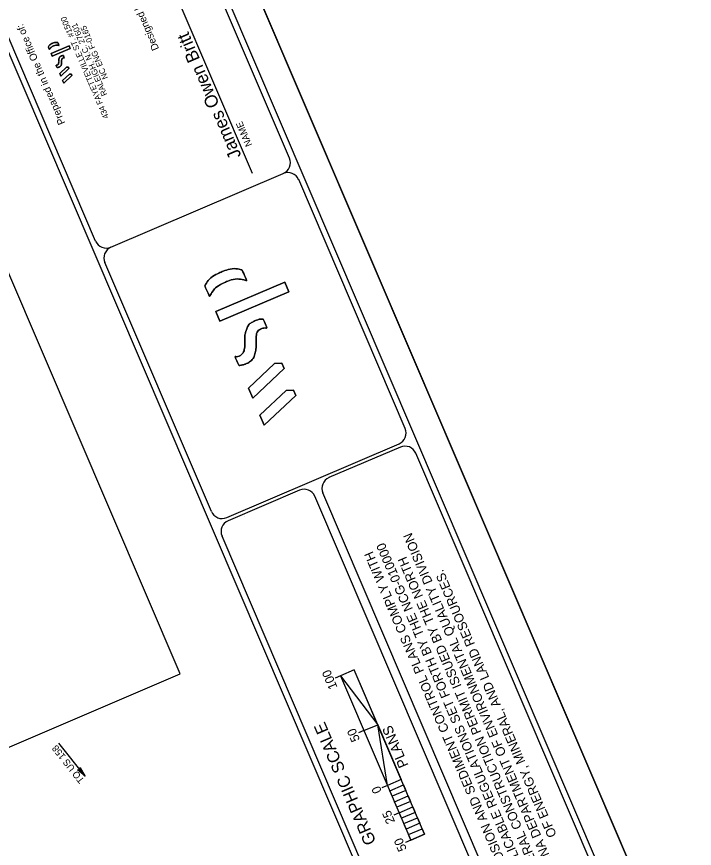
# Model space of a CAD drawing. Extents: x 1550250 to 1553148, y 808916 to 812359.
# Drawn here: x 1552151 to 1553148, y 809907 to 811132 of the extents above; entities that cross this region are included whole.
import ezdxf

# ---------------------------------------------------------------- set-up
doc = ezdxf.new("R2010")
doc.units = 0
for name, color, linetype in [('_P_RDY_Guardrail_Anchor_Unit_Cell', 7, 'Continuous'), ('Default', 7, 'Continuous'), ('Old_Level_46', 7, 'Continuous'), ('P_RDY_Bridge_Approach_Slab_Hatching', 7, 'Continuous'), ('P_RDY_Shade_Light', 7, 'Continuous'), ('Prop DSN Text', 7, 'Continuous'), ('Prop Terminator Cell', 7, 'Continuous'), ('Scratch_Level_0', 7, 'Continuous'), ('Sheet Title CELL', 7, 'Continuous'), ('Sheet_Plan_CELL', 7, 'Continuous'), ('Sheet_Title_CELL', 7, 'Continuous')]:
    doc.layers.add(name, color=color, linetype=linetype)

msp = doc.modelspace()

# ---------------------------------------------------------------- linework, layer by layer
at = {"layer": '_P_RDY_Guardrail_Anchor_Unit_Cell'}
msp.add_line((1552706.9, 809975.9), (1552727.1, 809984.5), dxfattribs=at)
for points in [[(1552627.5, 810161.4), (1552682.2, 810089.3), (1552647.7, 810170)], [(1552696.6, 810000.1), (1552682.2, 810089.3), (1552716.7, 810008.7)], [(1552703.5, 809984), (1552700, 809992), (1552720.2, 810000.7), (1552723.6, 809992.6)], [(1552710.4, 809967.8), (1552706.9, 809975.9), (1552727.1, 809984.5), (1552730.5, 809976.5)], [(1552717.3, 809951.7), (1552713.8, 809959.8), (1552734, 809968.4), (1552737.4, 809960.3)], [(1552724.2, 809935.6), (1552720.7, 809943.7), (1552740.9, 809952.3), (1552744.3, 809944.2)], [(1552731.1, 809919.5), (1552727.6, 809927.5), (1552747.8, 809936.2), (1552751.2, 809928.1)]]:
    msp.add_lwpolyline(points, close=True, dxfattribs=at)
at = {"layer": 'Default'}
for p, q in [((1552201.4, 811077.7), (1552227.9, 811089)), ((1552229.5, 811085.3), (1552203, 811074)), ((1552227.9, 811089), (1552229.5, 811085.3)), ((1552203, 811074), (1552201.4, 811077.7)), ((1552214, 811048.2), (1552224, 811057.7)), ((1552215.6, 811044.4), (1552214, 811048.2)), ((1552227.7, 811055.8), (1552215.6, 811044.4)), ((1552218.4, 811037.9), (1552228.4, 811047.3)), ((1552224, 811057.7), (1552226.8, 811057.8)), ((1552226.8, 811057.8), (1552227.7, 811055.8)), ((1552228.4, 811047.3), (1552231.2, 811047.5)), ((1552231.2, 811047.5), (1552232.1, 811045.4)), ((1552220, 811034), (1552218.4, 811037.9)), ((1552232.1, 811045.4), (1552220, 811034)), ((1552443.9, 810697.7), (1552545.5, 810741)), ((1552545.5, 810741), (1552551.5, 810726.9)), ((1552551.5, 810726.9), (1552449.9, 810683.6)), ((1552449.9, 810683.6), (1552443.9, 810697.7)), ((1552491.9, 810584.8), (1552530.4, 810621.1)), ((1552530.4, 810621.1), (1552541.3, 810621.6)), ((1552541.3, 810621.6), (1552544.6, 810613.7)), ((1552544.6, 810613.7), (1552498.2, 810570)), ((1552498.2, 810570), (1552491.9, 810584.8)), ((1552508.8, 810545.2), (1552547.3, 810581.4)), ((1552547.3, 810581.4), (1552558.1, 810581.9)), ((1552558.1, 810581.9), (1552561.5, 810574.1)), ((1552561.5, 810574.1), (1552515.1, 810530.4)), ((1552515.1, 810530.4), (1552508.8, 810545.2))]:
    msp.add_line(p, q, dxfattribs=at)
for points in [[(1552227.9, 811089), (1552201.4, 811077.7), (1552203, 811074), (1552229.5, 811085.3), (1552227.9, 811089)], [(1552214, 811048.2), (1552215.6, 811044.4), (1552227.7, 811055.8), (1552226.8, 811057.8), (1552224, 811057.7), (1552214, 811048.2)], [(1552218.4, 811037.9), (1552220, 811034), (1552232.1, 811045.4), (1552231.2, 811047.5), (1552228.4, 811047.3), (1552218.4, 811037.9)], [(1552545.5, 810741), (1552443.9, 810697.7), (1552449.9, 810683.6), (1552551.5, 810726.9), (1552545.5, 810741)], [(1552491.9, 810584.8), (1552498.2, 810570), (1552544.6, 810613.7), (1552541.3, 810621.6), (1552530.4, 810621.1), (1552491.9, 810584.8)], [(1552508.8, 810545.2), (1552515.1, 810530.4), (1552561.5, 810574.1), (1552558.1, 810581.9), (1552547.3, 810581.4), (1552508.8, 810545.2)]]:
    msp.add_lwpolyline(points, dxfattribs=at)
for points in [[(1552205.1, 811089), (1552202, 811087.8), (1552200, 811085.6), (1552199, 811083.4), (1552199, 811083.4), (1552197.2, 811087.6), (1552197.2, 811087.6), (1552198.3, 811089.7), (1552200.8, 811091.8), (1552203.4, 811092.9), (1552203.4, 811092.9), (1552203.4, 811092.9), (1552203.4, 811092.9), (1552206.1, 811094), (1552209.3, 811094.4), (1552211.5, 811093.7), (1552211.5, 811093.7), (1552213.3, 811089.6), (1552213.3, 811089.6), (1552211.1, 811090.3), (1552208.1, 811090.3), (1552205.1, 811089), (1552205.1, 811089), (1552205.1, 811089), (1552205.1, 811089)], [(1552205.1, 811089), (1552205.1, 811089), (1552205.1, 811089), (1552205.1, 811089), (1552208.1, 811090.3), (1552211.1, 811090.3), (1552213.3, 811089.6), (1552213.3, 811089.6), (1552211.5, 811093.7), (1552211.5, 811093.7), (1552209.3, 811094.4), (1552206.1, 811094), (1552203.4, 811092.9), (1552203.4, 811092.9), (1552203.4, 811092.9), (1552203.4, 811092.9), (1552200.8, 811091.8), (1552198.3, 811089.7), (1552197.2, 811087.6), (1552197.2, 811087.6), (1552199, 811083.4), (1552199, 811083.4), (1552200, 811085.6), (1552202, 811087.8), (1552205.1, 811089)], [(1552212.5, 811057.5), (1552211.8, 811057.2), (1552211, 811057), (1552210.2, 811057), (1552210.2, 811057), (1552208.8, 811060.4), (1552208.8, 811060.4), (1552209.4, 811060.4), (1552210.4, 811060.5), (1552211.2, 811061.2), (1552211.9, 811061.8), (1552212.3, 811062.6), (1552212.4, 811063.6), (1552212.6, 811064.7), (1552212.5, 811065.8), (1552212.5, 811066.9), (1552212.6, 811068.1), (1552212.6, 811069.2), (1552213, 811070.3), (1552213.5, 811071.9), (1552214.4, 811073.2), (1552216, 811074), (1552216.1, 811074), (1552216.3, 811074.1), (1552216.5, 811074.2), (1552217.5, 811074.6), (1552218.5, 811074.9), (1552219.6, 811074.8), (1552219.6, 811074.8), (1552221.1, 811071.4), (1552221.1, 811071.4), (1552220.4, 811071.5), (1552219.4, 811071.4), (1552218.7, 811071), (1552217, 811070.1), (1552216.9, 811067.5), (1552216.9, 811065.3), (1552216.9, 811065), (1552216.9, 811064.6), (1552216.9, 811064.3), (1552216.8, 811063.3), (1552216.7, 811062.4), (1552216.5, 811061.4), (1552216.2, 811060.4), (1552215.8, 811059.6), (1552215.1, 811058.9), (1552214.4, 811058.3), (1552213.6, 811057.9), (1552212.8, 811057.5), (1552212.7, 811057.5), (1552212.6, 811057.5), (1552212.5, 811057.5)], [(1552212.5, 811057.5), (1552212.6, 811057.5), (1552212.7, 811057.5), (1552212.8, 811057.5), (1552213.6, 811057.9), (1552214.4, 811058.3), (1552215.1, 811058.9), (1552215.8, 811059.6), (1552216.2, 811060.4), (1552216.5, 811061.4), (1552216.7, 811062.4), (1552216.8, 811063.3), (1552216.9, 811064.3), (1552216.9, 811064.6), (1552216.9, 811065), (1552216.9, 811065.3), (1552216.9, 811067.5), (1552217, 811070.1), (1552218.7, 811071), (1552219.4, 811071.4), (1552220.4, 811071.5), (1552221.1, 811071.4), (1552221.1, 811071.4), (1552219.6, 811074.8), (1552219.6, 811074.8), (1552218.5, 811074.9), (1552217.5, 811074.6), (1552216.5, 811074.2), (1552216.3, 811074.1), (1552216.1, 811074), (1552216, 811074), (1552214.4, 811073.2), (1552213.5, 811071.9), (1552213, 811070.3), (1552212.6, 811069.2), (1552212.6, 811068.1), (1552212.5, 811066.9), (1552212.5, 811065.8), (1552212.6, 811064.7), (1552212.4, 811063.6), (1552212.3, 811062.6), (1552211.9, 811061.8), (1552211.2, 811061.2), (1552210.4, 811060.5), (1552209.4, 811060.4), (1552208.8, 811060.4), (1552208.8, 811060.4), (1552210.2, 811057), (1552210.2, 811057), (1552211, 811057), (1552211.8, 811057.2), (1552212.5, 811057.5)], [(1552457.9, 810741), (1552446.3, 810736.1), (1552438.5, 810727.8), (1552434.6, 810719.6), (1552434.6, 810719.6), (1552427.7, 810735.6), (1552427.7, 810735.6), (1552431.9, 810743.6), (1552441.4, 810751.5), (1552451.6, 810755.8), (1552451.6, 810755.8), (1552451.6, 810755.9), (1552451.6, 810755.9), (1552461.8, 810760.2), (1552474.1, 810761.6), (1552482.7, 810759), (1552482.7, 810759), (1552489.6, 810743), (1552489.6, 810743), (1552480.9, 810745.8), (1552469.5, 810746), (1552457.9, 810741), (1552457.9, 810741), (1552457.9, 810741), (1552457.9, 810741)], [(1552457.9, 810741), (1552457.9, 810741), (1552457.9, 810741), (1552457.9, 810741), (1552469.5, 810746), (1552480.9, 810745.8), (1552489.6, 810743), (1552489.6, 810743), (1552482.7, 810759), (1552482.7, 810759), (1552474.1, 810761.6), (1552461.8, 810760.2), (1552451.6, 810755.9), (1552451.6, 810755.9), (1552451.6, 810755.8), (1552451.6, 810755.8), (1552441.4, 810751.5), (1552431.9, 810743.6), (1552427.7, 810735.6), (1552427.7, 810735.6), (1552434.6, 810719.6), (1552434.6, 810719.6), (1552438.5, 810727.8), (1552446.3, 810736.1), (1552457.9, 810741)], [(1552486.5, 810620.1), (1552483.6, 810619.2), (1552480.6, 810618.5), (1552477.6, 810618.6), (1552477.6, 810618.6), (1552472.1, 810631.5), (1552472.1, 810631.5), (1552474.5, 810631.2), (1552478.5, 810631.7), (1552481.5, 810634.4), (1552484.3, 810636.8), (1552485.5, 810639.9), (1552486.1, 810643.5), (1552486.8, 810647.7), (1552486.4, 810652.1), (1552486.5, 810656.3), (1552486.7, 810660.7), (1552486.9, 810665.1), (1552488.3, 810669.4), (1552490.3, 810675.6), (1552493.8, 810680.3), (1552499.6, 810683.3), (1552500.3, 810683.6), (1552501, 810684), (1552501.7, 810684.3), (1552505.5, 810685.9), (1552509.5, 810686.9), (1552513.6, 810686.6), (1552513.6, 810686.6), (1552519.2, 810673.4), (1552519.2, 810673.4), (1552516.4, 810673.7), (1552513, 810673.5), (1552510.3, 810672.1), (1552503.5, 810668.7), (1552503.3, 810658.6), (1552503.2, 810650.2), (1552503.2, 810648.9), (1552503.2, 810647.6), (1552503.1, 810646.4), (1552503, 810642.7), (1552502.6, 810638.9), (1552501.5, 810635.3), (1552500.4, 810631.6), (1552499, 810628.5), (1552496.2, 810625.8), (1552493.8, 810623.4), (1552490.8, 810621.7), (1552487.6, 810620.5), (1552487.2, 810620.4), (1552486.9, 810620.2), (1552486.5, 810620.1)], [(1552486.5, 810620.1), (1552486.9, 810620.2), (1552487.2, 810620.4), (1552487.6, 810620.5), (1552490.8, 810621.7), (1552493.8, 810623.4), (1552496.2, 810625.8), (1552499, 810628.5), (1552500.4, 810631.6), (1552501.5, 810635.3), (1552502.6, 810638.9), (1552503, 810642.7), (1552503.1, 810646.4), (1552503.2, 810647.6), (1552503.2, 810648.9), (1552503.2, 810650.2), (1552503.3, 810658.6), (1552503.5, 810668.7), (1552510.3, 810672.1), (1552513, 810673.5), (1552516.4, 810673.7), (1552519.2, 810673.4), (1552519.2, 810673.4), (1552513.6, 810686.6), (1552513.6, 810686.6), (1552509.5, 810686.9), (1552505.5, 810685.9), (1552501.7, 810684.3), (1552501, 810684), (1552500.3, 810683.6), (1552499.6, 810683.3), (1552493.8, 810680.3), (1552490.3, 810675.6), (1552488.3, 810669.4), (1552486.9, 810665.1), (1552486.7, 810660.7), (1552486.5, 810656.3), (1552486.4, 810652.1), (1552486.8, 810647.7), (1552486.1, 810643.5), (1552485.5, 810639.9), (1552484.3, 810636.8), (1552481.5, 810634.4), (1552478.5, 810631.7), (1552474.5, 810631.2), (1552472.1, 810631.5), (1552472.1, 810631.5), (1552477.6, 810618.6), (1552477.6, 810618.6), (1552480.6, 810618.5), (1552483.6, 810619.2), (1552486.5, 810620.1)]]:
    msp.add_open_spline(points, degree=3, dxfattribs=at)
at = {"layer": 'Old_Level_46'}
msp.add_line((1552485.8, 810395.8), (1552485.8, 810395.8), dxfattribs=at)
at = {"layer": 'P_RDY_Bridge_Approach_Slab_Hatching'}
for p, q in [((1552647.7, 810170), (1552627.5, 810161.4)), ((1552751.2, 809928.1), (1552647.7, 810170)), ((1552627.5, 810161.4), (1552619.5, 810157.9)), ((1552627.5, 810161.4), (1552731.1, 809919.5)), ((1552662, 810080.7), (1552654, 810077.3)), ((1552662, 810080.7), (1552682.2, 810089.3)), ((1552696.6, 810000.1), (1552688.5, 809996.6)), ((1552713.8, 809959.8), (1552705.8, 809956.3)), ((1552731.1, 809919.5), (1552723, 809916)), ((1552731.1, 809919.5), (1552751.2, 809928.1)), ((1552731.1, 809919.5), (1552731.1, 809919.5)), ((1552723, 809916), (1552723, 809916))]:
    msp.add_line(p, q, dxfattribs=at)
at = {"layer": 'P_RDY_Shade_Light'}
msp.add_line((1552498, 810901.3), (1552286.1, 811396.3), dxfattribs=at)
at = {"layer": 'Prop DSN Text'}
msp.add_line((1552251.4, 810013.4), (1552213, 810062), dxfattribs=at)
at = {"layer": 'Prop Terminator Cell'}
msp.add_lwpolyline([(1552244.4, 810026.2), (1552251.4, 810013.4), (1552240.4, 810023.1), (1552243.5, 810023.3)], close=True, dxfattribs=at)
at = {"layer": 'Scratch_Level_0'}
msp.add_line((1553148.4, 809662.7), (1551994.4, 812358.6), dxfattribs=at)
msp.add_lwpolyline([(1553148.4, 809662.7), (1551994.4, 812358.6), (1550250, 811611.9), (1551404, 808916)], close=True, dxfattribs=at)
at = {"layer": 'Sheet_Plan_CELL'}
msp.add_lwpolyline([(1551190.2, 811336.1), (1551800.2, 809911.1), (1552391.4, 810164.1), (1551781.4, 811589.2)], close=True, dxfattribs=at)
at = {"layer": 'Sheet_Title_CELL'}
for p, q in [((1553086.3, 809698.2), (1551984, 812273.4)), ((1552747.8, 809656.4), (1551686.1, 812136.6)), ((1552266.8, 810801.6), (1552059.9, 811285.3)), ((1552289.5, 810792.5), (1552543.2, 810901.1)), ((1552289.5, 810792.5), (1552543.2, 810901.1)), ((1552437.3, 810403.5), (1552280.5, 810770.1)), ((1552460, 810394.4), (1552713.7, 810503)), ((1552715.6, 810498.3), (1552610.5, 810453.3)), ((1553041.1, 809782), (1552738.3, 810489.2)), ((1552567.2, 810434.7), (1552462, 810389.7)), ((1552892.6, 809718.4), (1552589.8, 810425.7)), ((1552904.2, 809723.4), (1552601.4, 810430.6)), ((1552755.7, 809659.8), (1552453, 810367.1))]:
    msp.add_line(p, q, dxfattribs=at)
for points in [[(1552552.2, 810923.8), (1552345.4, 811407.5)], [(1552722.7, 810525.6), (1552566, 810892.2)]]:
    msp.add_lwpolyline(points, dxfattribs=at)
for centre, start, end in [((1552536.4, 810917), 293.1736, 23.1736), ((1552550, 810885.2), 23.1736, 113.1736), ((1552282.7, 810808.4), 203.1736, 293.1736), ((1552296.2, 810776.6), 113.1736, 203.1736), ((1552706.9, 810518.9), 293.1736, 23.1736), ((1552722.4, 810482.4), 23.1736, 113.1736), ((1552617.3, 810437.4), 113.1736, 203.1736), ((1552573.9, 810418.9), 23.1736, 113.1736), ((1552453.1, 810410.2), 203.1736, 293.1736), ((1552468.8, 810373.9), 113.1736, 203.1736)]:
    msp.add_arc(centre, 17.2, start, end, dxfattribs=at)

# ---------------------------------------------------------------- texts
at = {"layer": '_P_RDY_Guardrail_Anchor_Unit_Cell'}
for s, height, p in [('100', 13.16, (1552623.2, 810144.7)), ('50', 13.16, (1552656.3, 810067.4)), ('0', 13.2, (1552688.5, 809991.4)), ('25', 13.16, (1552708, 809946.6)), ('50', 13.16, (1552725.3, 809906.1))]:
    msp.add_text(s, height=height, rotation=113.1736, dxfattribs=at).set_placement(p)
at = {"layer": 'Old_Level_46'}
for s, height, p in [('Designed by:', 10.734, (1552360.5, 811084.8)), ('Prepared in the Office of:', 10.734, (1552222.4, 810975.5)), ('James Owen Britt', 18.916, (1552481.8, 810927.2)), ('NAME', 10.05, (1552497.6, 810943.2)), ('CAROLINA DEPARTMENT OF ENVIRONMENTAL QUALITY DIVISION ', 13.638, (1552961.9, 809835.7)), ('THE APPLICABLE REGULATIONS SET FORTH BY THE NCG-010000 ', 13.638, (1552920.6, 809824.7)), ('THESE EROSION AND SEDIMENT CONTROL PLANS COMPLY WITH', 13.638, (1552904.9, 809807.5)), ('GENERAL CONSTRUCTION PERMIT ISSUED BY THE NORTH ', 13.638, (1552931.2, 809853.8)), ('OF ENERGY, MINERAL, AND LAND RESOURCES.', 13.638, (1552946, 809926.8)), ('GRAPHIC SCALE', 17.866, (1552680.3, 809916.7))]:
    msp.add_text(s, height=height, rotation=113.1736, dxfattribs=at).set_placement(p)
at = {"layer": 'P_RDY_Bridge_Approach_Slab_Hatching'}
msp.add_text('PLANS', height=14.91, rotation=113.1736, dxfattribs=at).set_placement((1552727.8, 810029.7))
at = {"layer": 'Prop DSN Text'}
msp.add_text('TO US 158', height=10, rotation=128.2468, dxfattribs=at).set_placement((1552251, 810007.9))
at = {"layer": 'Sheet Title CELL'}
for s, p in [('434 FAYETTEVILLE ST. #1500', (1552286.6, 810984)), ('RALEIGH, N.C. 27601', (1552284.2, 811017.4)), ('NC ENG F-0165', (1552285.5, 811042))]:
    msp.add_text(s, height=8.625, rotation=113.1759, dxfattribs=at).set_placement(p)

doc.saveas('drawing.dxf')
